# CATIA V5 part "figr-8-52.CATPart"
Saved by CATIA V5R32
Part number: Part1
Bounding box of the stored display mesh (mm): x -37.5 to 37.5, y -150 to 150, z 0 to 10
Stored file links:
  D:\PROJECTS\Project 2022\CATIA V5 6R 2022\Resources\Part Files\c08_catia_v5_6r2022_prt\figr-8-52.CATPart
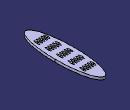
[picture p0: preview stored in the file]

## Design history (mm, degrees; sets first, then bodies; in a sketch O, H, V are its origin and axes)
Body1 (main body)
  Sketch1 on xy-plane, origin (0, 0, 0), H (1, 0, 0), V (0, 1, 0)
    circle A1 centre (0, 0) radius 75
    point P1 (0, 75)
    radius A1 = 75
    coincidence: A1 P1, P1 V
  Pad1: profile Sketch1, direction (0, 0, 1), length 10
  Sketch2 on face of Pad1, origin (0, 0, 10), H (1, 0, 0), V (0, 1, 0)
    circle A1 centre (35, -45) radius 6
    point P1 (35, -45)
    distance P1 H = 45
    distance V P1 = 35
    radius A1 = 6
  Pocket1: profile Sketch2, direction (0, 0, -1), through (limit type 3)
  RectPattern1: of Pocket1, direction 1 instances 5, spacing 19, along xy-plane reversed, direction 2 instances 5, spacing 22, along xy-plane
  Affinity1: ToTransfor RectPattern1, RatioX 0.5, RatioY 2, RatioZ 1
